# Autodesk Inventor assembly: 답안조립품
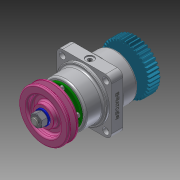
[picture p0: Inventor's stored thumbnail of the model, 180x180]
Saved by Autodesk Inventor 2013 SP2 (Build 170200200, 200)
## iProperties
Created: 2023-10
Part Number: 답안조립품
Document SubType Name: Assembly
Designer: i
Author: i
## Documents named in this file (12)
- C:\Users\i\Desktop\731006V1008\답안조립품.iam
- C:\Users\i\Desktop\731006V1008\본체.ipt
- C:\Users\i\Desktop\731006V1008\V벨트풀리.ipt
- C:\Users\i\Desktop\731006V1008\너트 M12x1.25.ipt
- C:\Users\i\Desktop\731006V1008\베어링 6204.ipt
- C:\Users\i\Desktop\731006V1008\볼트 M4x0.7.ipt
- C:\Users\i\Desktop\731006V1008\스퍼기어.ipt
- C:\Users\i\Desktop\731006V1008\오일실 20x35x8.ipt
- C:\Users\i\Desktop\731006V1008\와셔 12x24.ipt
- C:\Users\i\Desktop\731006V1008\축.ipt
- C:\Users\i\Desktop\731006V1008\커버.ipt
- C:\Users\i\Desktop\731006V1008\키 5x5.ipt
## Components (1 placed, 1 different names)
1. V벨트풀리:1
